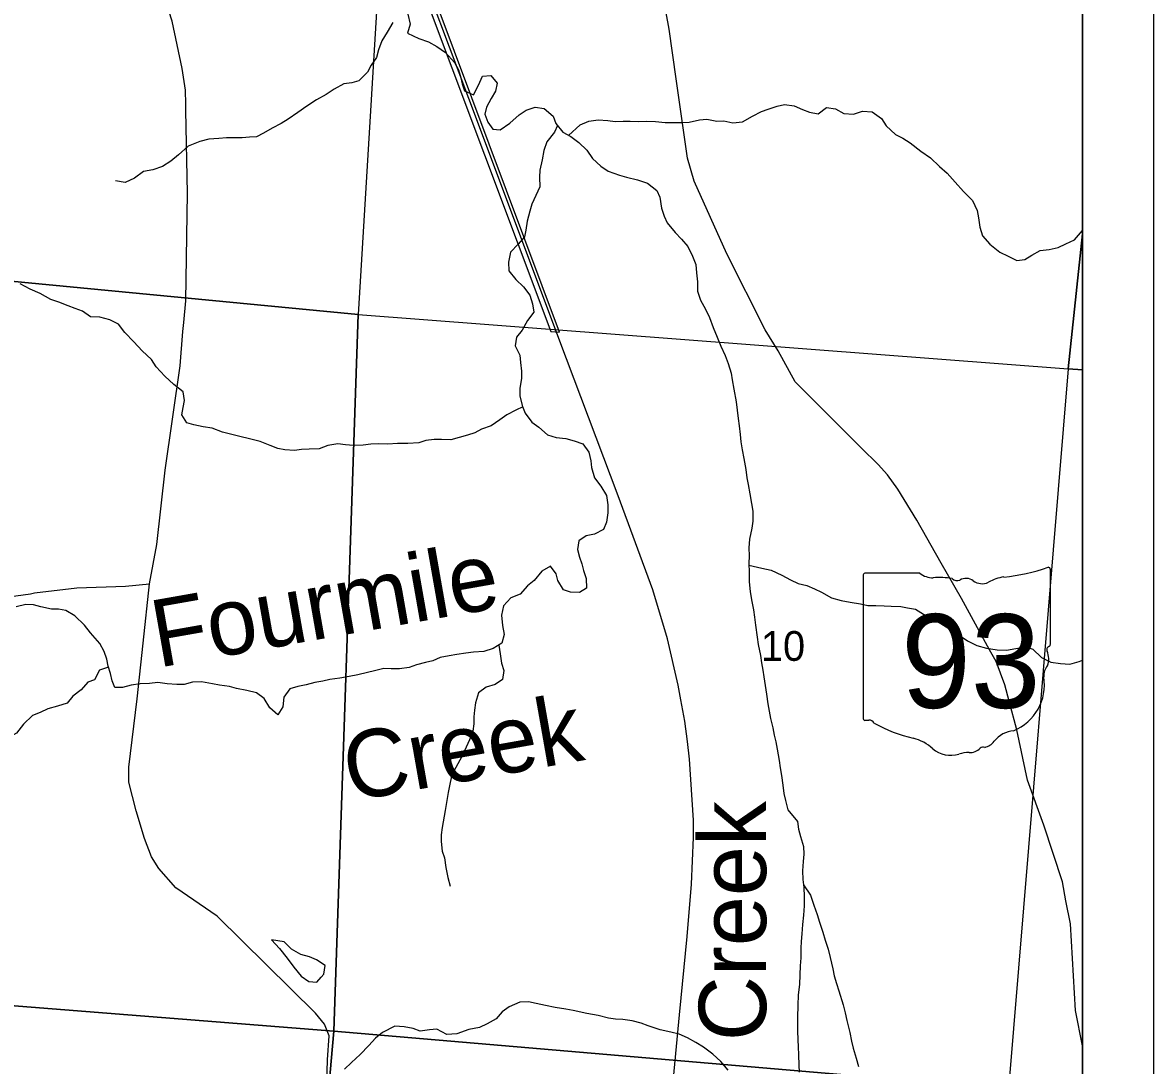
# Model space of a CAD drawing. Extents: x 0 to 34, y 0 to 22.
# Drawn here: x 28.825 to 30.417, y 17.615 to 19.082 of the extents above; entities that cross this region are included whole.
import ezdxf

# ---------------------------------------------------------------- set-up
doc = ezdxf.new("R2010")
doc.units = 0
for name, color, linetype in [('GM_X_Corporation', 7, 'Continuous'), ('GM_X_County_Road', 7, 'Continuous'), ('GM_X_Major_River', 7, 'Continuous'), ('GM_X_Major_River_Text', 7, 'Continuous'), ('GM_X_Minor_Lake', 7, 'Continuous'), ('GM_X_Minor_River', 7, 'Continuous'), ('GM_X_Minor_River_Text', 7, 'Continuous'), ('GM_X_Rail_Line', 7, 'Continuous'), ('GM_X_Section_Text', 7, 'Continuous'), ('GM_X_State_Location', 7, 'Continuous'), ('GM_X_State_Route', 7, 'Continuous'), ('GM_X_State_Shield', 7, 'Continuous'), ('SH_Data', 7, 'Continuous')]:
    doc.layers.add(name, color=color, linetype=linetype)

msp = doc.modelspace()

# ---------------------------------------------------------------- linework, layer by layer
at = {"layer": 'GM_X_Corporation'}
for points in [[(28.4917, 19.7627), (29.3585, 19.6871), (29.2972, 18.6715), (28.6566, 18.7331), (28.2889, 18.7562), (28.3876, 19.7694)], [(30.3167, 18.7853), (30.3167, 19.5984), (29.4415, 19.6802), (29.3585, 19.6871), (29.2972, 18.6715), (30.2969, 18.5954)], [(30.3167, 18.5939), (30.3167, 18.7853), (30.2969, 18.5954)], [(28.2889, 18.7562), (28.6566, 18.7331), (29.2972, 18.6715), (29.263, 17.6631), (28.2741, 17.7417), (28.2146, 17.7472)], [(30.2969, 18.5954), (30.2127, 17.5822), (29.263, 17.6631), (29.2972, 18.6715)], [(30.3167, 17.5734), (30.3167, 18.5939), (30.2969, 18.5954), (30.2127, 17.5822)], [(28.2741, 17.7417), (29.263, 17.6631), (29.176, 16.6858), (28.199, 16.7653)], [(30.2127, 17.5822), (30.115, 16.6136), (29.176, 16.6858), (29.263, 17.6631)]]:
    msp.add_lwpolyline(points, close=True, dxfattribs=at)
for points in [[(25.8273, 14.1), (30.3167, 14.1), (30.3167, 19.5906)], [(29.2436, 19.5128), (29.5681, 18.6478), (29.5806, 18.6469), (29.2591, 19.5062)]]:
    msp.add_lwpolyline(points, dxfattribs=at)
at = {"layer": 'GM_X_County_Road'}
for points in [[(29.0546, 18.9586), (29.0544, 18.9674), (29.0538, 18.9872), (29.0494, 19.018), (29.0351, 19.0845), (29.0176, 19.1401), (29.0044, 19.1782), (28.9965, 19.2049), (28.9863, 19.2516), (28.9753, 19.3368), (28.9739, 19.3586), (28.9753, 19.3846), (28.9842, 19.4654), (28.99, 19.5328), (28.9921, 19.5966), (28.9916, 19.6165)], [(29.0033, 18.2928), (29.0138, 18.3478), (29.0252, 18.4526), (29.0463, 18.5996), (29.0503, 18.6477), (29.0517, 18.6603), (29.0543, 18.691), (29.057, 18.8425), (29.0546, 18.9586)], [(28.7943, 18.2729), (28.8356, 18.2786), (28.8415, 18.2798), (28.901, 18.2871), (28.9697, 18.2896), (29.0033, 18.2928)], [(29.2523, 17.5746), (29.254, 17.6231), (29.2561, 17.6565), (29.2496, 17.6731), (29.2371, 17.6886), (29.0985, 17.825), (29.0405, 17.8647), (29.0165, 17.892), (29.0063, 17.9084), (28.9964, 17.9344), (28.9846, 17.9734), (28.9742, 18.0138), (28.9742, 18.0346), (28.9859, 18.131), (28.9946, 18.209), (29.0033, 18.2928)]]:
    msp.add_lwpolyline(points, dxfattribs=at)
at = {"layer": 'GM_X_Major_River'}
for points in [[(29.3672, 19.0944), (29.3701, 19.0804), (29.3666, 19.0675), (29.3824, 19.0602), (29.396, 19.0551), (29.4077, 19.0489), (29.4198, 19.0401), (29.4329, 19.026), (29.4382, 19.0161), (29.4411, 19.0066), (29.4433, 18.9963), (29.4466, 18.9864), (29.4595, 18.9806), (29.4664, 18.9942), (29.4722, 19.0071), (29.484, 19.0081), (29.493, 18.9971), (29.4902, 18.9857), (29.4841, 18.9755), (29.4779, 18.9634), (29.4755, 18.9536), (29.4796, 18.9425), (29.4867, 18.9322), (29.4969, 18.9314), (29.5107, 18.9408), (29.5237, 18.9524), (29.5336, 18.9592), (29.5465, 18.9636), (29.559, 18.9616), (29.5714, 18.9505), (29.5755, 18.9406), (29.5852, 18.928), (29.5965, 18.9219), (29.6078, 18.9138), (29.6191, 18.9031), (29.627, 18.8913), (29.6386, 18.8802), (29.6492, 18.8733), (29.6651, 18.8678), (29.6749, 18.8651), (29.6904, 18.8612), (29.7044, 18.8565), (29.7176, 18.8462), (29.7216, 18.8366), (29.7242, 18.8211), (29.7279, 18.81), (29.7323, 18.8005), (29.7436, 18.7871), (29.7522, 18.7776), (29.7612, 18.7673), (29.7676, 18.7539), (29.7724, 18.7418), (29.7734, 18.7304), (29.7748, 18.7175), (29.7747, 18.7046), (29.7792, 18.692), (29.7863, 18.679), (29.7918, 18.6676), (29.797, 18.6532), (29.8026, 18.6398), (29.8078, 18.6273), (29.8138, 18.6139), (29.8182, 18.6025), (29.8223, 18.5892), (29.8237, 18.5797), (29.8262, 18.5664), (29.8291, 18.5489)], [(29.8291, 18.5489), (29.8309, 18.5368), (29.8323, 18.5254), (29.8334, 18.5148), (29.8348, 18.5026), (29.8359, 18.4924), (29.8377, 18.4813), (29.8402, 18.4688), (29.8427, 18.4536), (29.8445, 18.4418), (29.846, 18.4323), (29.8485, 18.4194), (29.851, 18.4057), (29.8525, 18.3947), (29.8527, 18.381), (29.8515, 18.3712), (29.848, 18.3553), (29.8471, 18.3431), (29.8474, 18.3321), (29.8473, 18.3211), (29.8476, 18.309), (29.8478, 18.2953), (29.8492, 18.2817), (29.851, 18.2703), (29.8536, 18.2562), (29.855, 18.2459), (29.8564, 18.2346), (29.8589, 18.2175), (29.8604, 18.2072), (29.8633, 18.192), (29.8651, 18.1814), (29.8669, 18.1711), (29.8683, 18.1616), (29.8701, 18.1498), (29.8719, 18.1373), (29.8737, 18.124), (29.8755, 18.1137), (29.8777, 18.1031), (29.881, 18.0898), (29.8828, 18.0799), (29.885, 18.0704), (29.8872, 18.0602), (29.8897, 18.0442), (29.8911, 18.0336), (29.8929, 18.0229), (29.8951, 18.0092), (29.8965, 17.9975), (29.8987, 17.9876), (29.902, 17.9747)], [(29.902, 17.9747), (29.9157, 17.9584), (29.9172, 17.9474), (29.9197, 17.9371), (29.9241, 17.923), (29.9244, 17.9124), (29.9236, 17.9018), (29.9227, 17.8886), (29.923, 17.8768), (29.9244, 17.8654), (29.925, 17.8529), (29.9249, 17.8396), (29.924, 17.8264), (29.9228, 17.8131), (29.9215, 17.8002), (29.9207, 17.7896), (29.9202, 17.7801), (29.9201, 17.7665), (29.9196, 17.7551), (29.9191, 17.7426), (29.9183, 17.729), (29.9166, 17.7142), (29.9161, 17.6994), (29.9156, 17.6831), (29.9158, 17.6638), (29.9161, 17.6509), (29.9164, 17.641), (29.917, 17.63), (29.9176, 17.6152), (29.9179, 17.6054)]]:
    msp.add_lwpolyline(points, dxfattribs=at)
at = {"layer": 'GM_X_Minor_Lake'}
for points in [[(29.1749, 17.7918), (29.1862, 17.7796), (29.1972, 17.766), (29.2063, 17.7531), (29.2168, 17.7406), (29.2274, 17.733), (29.2388, 17.7323), (29.2448, 17.739)], [(29.2448, 17.739), (29.2489, 17.7436), (29.2508, 17.7558), (29.2384, 17.7637), (29.2285, 17.7679), (29.2165, 17.7709), (29.2032, 17.7785), (29.193, 17.7887), (29.1749, 17.7918)]]:
    msp.add_lwpolyline(points, dxfattribs=at)
at = {"layer": 'GM_X_Minor_River'}
for points in [[(29.3461, 19.0827), (29.3381, 19.0691), (29.3305, 19.0566), (29.3255, 19.0441), (29.3229, 19.0331), (29.3156, 19.0225), (29.3103, 19.0127), (29.2981, 19.0002), (29.2883, 18.9976), (29.2769, 18.9961), (29.2633, 18.9889), (29.2519, 18.981), (29.2383, 18.9739), (29.225, 18.9648), (29.2121, 18.9561), (29.1984, 18.9463), (29.1889, 18.9403), (29.1761, 18.9339), (29.1639, 18.9267), (29.1541, 18.9214), (29.1442, 18.9211), (29.1336, 18.92), (29.1215, 18.9204), (29.1117, 18.9204), (29.1011, 18.9193), (29.0867, 18.9182), (29.0742, 18.9152), (29.0579, 18.9085), (29.0442, 18.8964), (29.0332, 18.8873), (29.0215, 18.8798), (29.0082, 18.8753), (28.9949, 18.8727), (28.9824, 18.8636), (28.9688, 18.8576), (28.9555, 18.8595)], [(29.5931, 18.9237), (29.6094, 18.9385), (29.6219, 18.9437), (29.6348, 18.9456), (29.6488, 18.9444), (29.659, 18.9432), (29.67, 18.9439), (29.6798, 18.9439), (29.6919, 18.9431), (29.7029, 18.9435), (29.7158, 18.943), (29.7294, 18.9419), (29.7532, 18.9418), (29.7631, 18.9425), (29.7775, 18.9455), (29.7881, 18.9466), (29.8021, 18.9439), (29.8119, 18.9442), (29.8248, 18.9412), (29.8384, 18.9426), (29.8524, 18.9505), (29.8649, 18.9573), (29.8744, 18.9607), (29.8869, 18.9648), (29.8975, 18.9671), (29.9107, 18.9651), (29.9225, 18.9602), (29.9327, 18.9563), (29.9448, 18.954), (29.9565, 18.9627), (29.969, 18.9608), (29.9807, 18.9543), (29.9943, 18.9535), (30.0072, 18.9576), (30.0209, 18.9568), (30.0337, 18.9473), (30.0405, 18.937), (30.0537, 18.9248), (30.0639, 18.9199), (30.0744, 18.9134), (30.0892, 18.9016), (30.1028, 18.892), (30.1156, 18.8799), (30.1261, 18.8707), (30.1375, 18.8578), (30.1491, 18.8445), (30.162, 18.8319), (30.1684, 18.8179), (30.1706, 18.8076), (30.1724, 18.7947), (30.1762, 18.7822), (30.1864, 18.7708), (30.2007, 18.7594), (30.212, 18.7536), (30.2245, 18.7475), (30.2355, 18.749), (30.2453, 18.755), (30.2571, 18.7618), (30.27, 18.7633), (30.2828, 18.7659), (30.2935, 18.7712), (30.3056, 18.7768), (30.3167, 18.7897)], [(29.5778, 18.9376), (29.5734, 18.928), (29.5628, 18.9147), (29.5586, 18.9022), (29.5563, 18.8893), (29.5528, 18.8746), (29.5524, 18.8651), (29.5527, 18.8514), (29.547, 18.8393), (29.5417, 18.8268), (29.539, 18.817), (29.5348, 18.803), (29.5332, 18.7904), (29.5313, 18.781), (29.5225, 18.7708), (29.5115, 18.7594), (29.5088, 18.7454), (29.5092, 18.7329), (29.519, 18.7211), (29.5299, 18.7104), (29.5389, 18.699), (29.5427, 18.6865), (29.5442, 18.6747), (29.5354, 18.6634), (29.5278, 18.6498), (29.5202, 18.6399), (29.5183, 18.6274), (29.5247, 18.6145), (29.5254, 18.6043), (29.5268, 18.5921), (29.5272, 18.5819), (29.5249, 18.5675), (29.5245, 18.5565), (29.5286, 18.5424), (29.5323, 18.5329), (29.5414, 18.52), (29.5516, 18.5132), (29.5636, 18.5021), (29.5757, 18.4987), (29.5893, 18.4971), (29.6014, 18.494), (29.6132, 18.4898), (29.6218, 18.4777), (29.6248, 18.4659), (29.6255, 18.4564), (29.6297, 18.4416), (29.6387, 18.4302), (29.6466, 18.4169), (29.6488, 18.4036), (29.6488, 18.3926), (29.6465, 18.3794), (29.6426, 18.3691), (29.6298, 18.3627), (29.618, 18.3601), (29.6078, 18.3533), (29.6058, 18.3408), (29.6088, 18.3302), (29.6118, 18.3207), (29.6141, 18.3112), (29.6182, 18.3002), (29.6185, 18.2865), (29.6087, 18.2805), (29.5962, 18.2809), (29.5863, 18.2844), (29.5784, 18.2973), (29.5758, 18.3068), (29.5679, 18.3174), (29.5558, 18.3106), (29.5451, 18.2974), (29.5356, 18.2898), (29.525, 18.2781), (29.5121, 18.2729), (29.5019, 18.2619), (29.4988, 18.2486), (29.5003, 18.2338), (29.5025, 18.2213), (29.4994, 18.2092), (29.4873, 18.2017), (29.474, 18.1975), (29.4596, 18.1964), (29.4487, 18.195), (29.4358, 18.1931), (29.4252, 18.1912), (29.4123, 18.189), (29.4021, 18.1845), (29.3918, 18.1819), (29.3793, 18.1785), (29.3687, 18.1751), (29.3555, 18.1729), (29.3437, 18.1729), (29.3332, 18.1734), (29.3203, 18.1704), (29.3104, 18.1681), (29.2968, 18.1648), (29.2843, 18.1621), (29.2714, 18.1599), (29.257, 18.1581), (29.2472, 18.1558), (29.2362, 18.1536), (29.2237, 18.1506), (29.2123, 18.1484)], [(29.5288, 18.5418), (29.5191, 18.5368), (29.5066, 18.5304), (29.4967, 18.5236), (29.4842, 18.5149), (29.4709, 18.5104), (29.4615, 18.5051), (29.4508, 18.5017), (29.4395, 18.4984), (29.4274, 18.4954), (29.4145, 18.4958), (29.4039, 18.4958), (29.3925, 18.4944), (29.3823, 18.491), (29.3672, 18.4899), (29.3524, 18.4899), (29.3388, 18.4892), (29.3252, 18.4897), (29.3149, 18.4893), (29.304, 18.4878), (29.2903, 18.4871), (29.2794, 18.4883), (29.2684, 18.4898), (29.2544, 18.4872), (29.2422, 18.4824), (29.2279, 18.482), (29.2173, 18.4817), (29.2074, 18.4802), (29.1938, 18.481), (29.184, 18.4833), (29.173, 18.4871), (29.159, 18.4929), (29.1443, 18.4967), (29.1303, 18.4998), (29.1061, 18.5059), (29.0913, 18.5117), (29.0789, 18.5136), (29.0656, 18.5163), (29.0558, 18.5194), (29.049, 18.5304), (29.0506, 18.5406), (29.0525, 18.5505), (29.0506, 18.5626), (29.0374, 18.5733), (29.025, 18.5847), (29.0129, 18.598), (29.0061, 18.6083), (28.9929, 18.6205), (28.9812, 18.6334), (28.9684, 18.6463), (28.9598, 18.6581), (28.9473, 18.6642), (28.9333, 18.6677), (28.9201, 18.6685), (28.9091, 18.6765), (28.8985, 18.6803), (28.8887, 18.6838), (28.8755, 18.6891), (28.8645, 18.6926), (28.8494, 18.701), (28.8354, 18.7071), (28.8214, 18.7147)], [(29.8473, 18.3189), (29.8654, 18.3149), (29.8786, 18.3118), (29.8937, 18.3049), (29.9058, 18.2981), (29.9164, 18.2931), (29.9289, 18.2904), (29.9395, 18.2854), (29.9493, 18.2809), (29.9636, 18.2729), (29.9769, 18.269), (29.9897, 18.2667), (30.0045, 18.2644), (30.0147, 18.2624), (30.026, 18.2624), (30.0374, 18.2616), (30.0476, 18.2612), (30.0609, 18.2608), (30.0707, 18.2588), (30.0817, 18.2569), (30.0968, 18.2478), (30.1111, 18.2405), (30.1251, 18.2321), (30.1398, 18.2226), (30.1549, 18.2123), (30.1681, 18.2058), (30.1818, 18.2023), (30.1965, 18.2), (30.2101, 18.1992), (30.223, 18.2018), (30.2366, 18.204), (30.2468, 18.2006), (30.2593, 18.1892), (30.2721, 18.1823), (30.2858, 18.1804), (30.299, 18.1796), (30.3123, 18.1833), (30.3167, 18.1854)], [(29.2123, 18.1484), (29.201, 18.145), (29.1926, 18.1333), (29.191, 18.1196), (29.1842, 18.1082), (29.1729, 18.1181), (29.1646, 18.1314), (29.154, 18.1394), (29.1404, 18.1425), (29.126, 18.1456), (29.1158, 18.1483), (29.1018, 18.1499), (29.092, 18.1518), (29.0765, 18.1549), (29.0636, 18.1545), (29.0519, 18.1512), (29.042, 18.1512), (29.028, 18.152), (29.0148, 18.1536), (29.0031, 18.1525), (28.9902, 18.1521), (28.9773, 18.1503), (28.9652, 18.1469), (28.9546, 18.1469), (28.9505, 18.1564), (28.9482, 18.1667), (28.9452, 18.1769), (28.943, 18.1868), (28.9396, 18.1974), (28.9332, 18.2085), (28.92, 18.2237), (28.9118, 18.2343), (28.8982, 18.2476), (28.8853, 18.2553), (28.8751, 18.2568), (28.8653, 18.2572), (28.8505, 18.2603), (28.8399, 18.263), (28.829, 18.2634), (28.8157, 18.2604)], [(29.495, 18.2064), (29.4971, 18.194), (29.4989, 18.1811), (29.5023, 18.1709), (29.5004, 18.158), (29.4901, 18.1508), (29.4773, 18.1471), (29.4663, 18.1392), (29.4624, 18.1251), (29.4609, 18.1149), (29.4597, 18.1054), (29.4597, 18.0956), (29.4585, 18.0853), (29.4539, 18.0732), (29.4493, 18.063), (29.4429, 18.0497), (29.4291, 18.024), (29.4268, 18.013), (29.4238, 17.999), (29.4196, 17.9738)], [(28.9456, 18.1756), (28.9327, 18.1713), (28.9259, 18.1577), (28.9164, 18.1543), (28.9073, 18.1433), (28.8955, 18.1346), (28.8872, 18.1248), (28.8739, 18.1207), (28.8603, 18.1166), (28.8493, 18.1117), (28.8387, 18.1075), (28.8261, 18.0954), (28.8159, 18.0826), (28.8034, 18.0754), (28.7957, 18.0629), (28.7934, 18.0497), (28.7949, 18.0356), (28.7941, 18.0227), (28.7872, 18.0102), (28.78, 17.9985), (28.7693, 17.9742)], [(29.4196, 17.9738), (29.4152, 17.95), (29.4137, 17.9394), (29.4137, 17.9299), (29.4155, 17.9166), (29.4185, 17.9071), (29.4207, 17.8935), (29.4233, 17.8794), (29.4266, 17.8673)], [(29.9239, 17.8691), (29.9338, 17.8544), (29.9386, 17.8407), (29.9431, 17.8274), (29.9465, 17.8168), (29.9513, 17.8027), (29.9547, 17.7914), (29.9588, 17.7784), (29.9617, 17.7671), (29.9654, 17.7511), (29.9673, 17.7413), (29.9703, 17.7302), (29.974, 17.72), (29.98, 17.7003), (29.9829, 17.6892), (29.9852, 17.6782), (29.9892, 17.6612), (29.9918, 17.649), (29.9941, 17.6395), (29.9982, 17.6251), (30.0015, 17.6137)], [(29.8182, 17.6081), (29.8077, 17.6207), (29.7964, 17.631), (29.7832, 17.6409), (29.7726, 17.6474), (29.7609, 17.6539), (29.7489, 17.6592), (29.7372, 17.6616), (29.7224, 17.665), (29.7054, 17.6708), (29.6956, 17.6743), (29.6828, 17.6777), (29.6696, 17.6797), (29.6594, 17.6801), (29.6496, 17.6813), (29.6348, 17.6851), (29.619, 17.6882), (29.5997, 17.6921), (29.5895, 17.6944), (29.5744, 17.6964), (29.5608, 17.6995), (29.5476, 17.7022), (29.537, 17.7045), (29.5245, 17.7038), (29.5098, 17.6975), (29.4999, 17.6903), (29.4912, 17.6805), (29.4787, 17.6737), (29.4677, 17.6685), (29.453, 17.6655), (29.4359, 17.6595), (29.4219, 17.6584), (29.4076, 17.6661), (29.3974, 17.665), (29.3842, 17.6632), (29.3743, 17.667), (29.3619, 17.6693), (29.3487, 17.6701), (29.3312, 17.6615), (29.3217, 17.6532), (29.3123, 17.643), (29.3001, 17.6306), (29.2876, 17.6189), (29.2777, 17.6098)]]:
    msp.add_lwpolyline(points, dxfattribs=at)
at = {"layer": 'GM_X_Rail_Line'}
msp.add_lwpolyline([(29.7071, 17.2403), (29.7493, 17.6862), (29.7603, 17.7964), (29.7664, 17.87), (29.769, 17.9356), (29.7694, 17.9601), (29.7635, 18.0458), (29.7608, 18.0706), (29.757, 18.0996), (29.7515, 18.1293), (29.7477, 18.15), (29.7326, 18.2154), (29.712, 18.2843), (29.6629, 18.4163), (29.5905, 18.6092), (29.4527, 18.9755), (29.2926, 19.4017)], dxfattribs=at)
at = {"layer": 'GM_X_State_Route'}
msp.add_lwpolyline([(30.3167, 17.6428), (30.3072, 17.6921), (30.2999, 17.8143), (30.2933, 17.8465), (30.2888, 17.8733), (30.2625, 17.9531), (30.2394, 18.0164), (30.2245, 18.0874), (30.2137, 18.1275), (30.2074, 18.1506), (30.1955, 18.1834), (30.1861, 18.1998), (30.1466, 18.2719), (30.1177, 18.3219), (30.0834, 18.3824), (30.0567, 18.4257), (30.0425, 18.4459), (30.0294, 18.4607), (30.0051, 18.4838), (29.9125, 18.5771), (29.8882, 18.6204), (29.8699, 18.6502), (29.8162, 18.7569), (29.7702, 18.8594), (29.7609, 18.8915), (29.745, 19.0033), (29.7349, 19.0729), (29.7257, 19.1248)], dxfattribs=at)
at = {"layer": 'GM_X_State_Shield'}
for p, q in [((30.2716, 18.2079), (30.2716, 18.3125)), ((30.008, 18.3041), (30.008, 18.104)), ((30.0878, 18.3076), (30.0106, 18.3076)), ((30.2716, 18.2079), (30.2716, 18.2079))]:
    msp.add_line(p, q, dxfattribs=at)
for centre, radius, start, end in [((30.1777, 18.5804), 0.2796, 275.8445, 288.9065), ((30.2687, 18.313), 0.00294, 351.8621, 97.738), ((30.011, 18.3046), 0.00305, 98.1301, 188.1301), ((30.1062, 18.3308), 0.0296, 231.6195, 271.1119), ((30.116, 18.1952), 0.1064, 80.4867, 94.9883), ((30.1401, 18.3056), 0.00855, 219.7921, 297.1024), ((30.1527, 18.2825), 0.0178, 54.4667, 119.1411), ((30.1756, 18.3142), 0.0214, 233.8562, 294.8282), ((30.2134, 18.2465), 0.0563, 97.3462, 120.7689), ((30.271, 18.2002), 0.00454, 107.944, 210.337), ((30.2421, 18.1869), 0.0273, 340.033, 23.6496), ((30.2685, 18.2075), 0.00314, 289.6038, 7.7341), ((30.2822, 18.1641), 0.0198, 136.8065, 186.9296), ((30.1934, 18.1507), 0.0699, 292.3089, 8.9858), ((30.011, 18.1036), 0.00308, 171.9584, 258.3066), ((30.0115, 18.1241), 0.0235, 267.339, 280.6039), ((30.0163, 18.0925), 0.00848, 29.7484, 93.2717), ((30.1234, 18.2723), 0.2019, 240.4129, 257.1985), ((30.2229, 18.0478), 0.0383, 94.4031, 142.5768), ((30.0632, 18.0141), 0.0632, 47.1842, 75.836), ((30.1743, 18.0846), 0.0226, 282.8732, 323.2771), ((30.1315, 18.0915), 0.0401, 230.7004, 286.2918), ((30.1547, 18.0223), 0.0329, 85.6951, 111.2099), ((30.1576, 18.0765), 0.0214, 268.777, 315.5493), ((30.1769, 18.0571), 0.00601, 65.7517, 132.6484)]:
    msp.add_arc(centre, radius, start, end, dxfattribs=at)
at = {"layer": 'SH_Data'}
for points in [[(23.4167, 21), (30.4167, 21), (30.4167, 14), (23.4167, 14)], [(23.5167, 20.9), (30.3167, 20.9), (30.3167, 14.1), (23.5167, 14.1)]]:
    msp.add_lwpolyline(points, close=True, dxfattribs=at)

# ---------------------------------------------------------------- texts
at = {"layer": 'GM_X_Major_River_Text'}
msp.add_text('Creek', height=0.09471, rotation=90.0003, dxfattribs=at).set_placement((29.8714, 17.6492))
at = {"layer": 'GM_X_Minor_River_Text'}
for s, rotation, p in [('Fourmile', 9.9988, (29.0154, 18.1745)), ('Creek', 9.9989, (29.2854, 17.9863))]:
    msp.add_text(s, height=0.0947, rotation=rotation, dxfattribs=at).set_placement(p)
at = {"layer": 'GM_X_Section_Text'}
msp.add_text('10', height=0.04186, rotation=0, dxfattribs=at).set_placement((29.8641, 18.1843))
at = {"layer": 'GM_X_State_Location'}
for s in ['s', 'r']:
    msp.add_text(s, height=0.000189, dxfattribs=at).set_placement((30.1368, 18.1908))
msp.add_text('93', height=0.000189, rotation=0, dxfattribs=at).set_placement((30.0891, 18.177))
at = {"layer": 'GM_X_State_Shield'}
msp.add_text('93', height=0.13184, dxfattribs=at).set_placement((30.0616, 18.1181))

doc.saveas('drawing.dxf')
